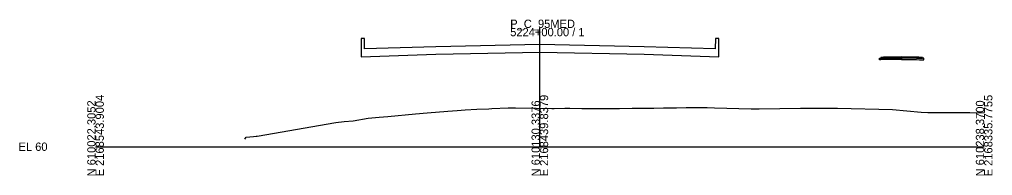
# Model space of a CAD drawing. Extents: x -26 to 303, y -10 to 10517.
# Drawn here: x -25.7 to 302.8, y 3990.3 to 4042.8 of the extents above; entities that cross this region are included whole.
import ezdxf

# ---------------------------------------------------------------- set-up
doc = ezdxf.new("R2010")
doc.units = 0
for name, color, linetype in [('RD_GPK_XS_Cell', 7, 'Continuous'), ('RD_PD_Final_TrvlWay', 7, 'Continuous'), ('RD_XS_Base', 7, 'Continuous'), ('RD_XS_ExGround', 7, 'Continuous'), ('RD_XS_Pave', 7, 'Continuous'), ('RD_XS_PaveOvlay_CP', 7, 'Continuous')]:
    doc.layers.add(name, color=color, linetype=linetype)

msp = doc.modelspace()

# ---------------------------------------------------------------- linework, layer by layer
at = {"layer": 'RD_GPK_XS_Cell'}
for p, q in [((150, 4000), (150, 4040)), ((0, 4000), (150, 4000)), ((150, 4000), (300, 4000))]:
    msp.add_line(p, q, dxfattribs=at)
at = {"layer": 'RD_PD_Final_TrvlWay'}
msp.add_lwpolyline([(114.83, 4031.13), (114.83, 4031.13), (150, 4031.83), (150, 4031.83), (150, 4031.83), (185.17, 4031.13), (185.17, 4031.13), (210.38, 4030.32), (210.38, 4036.41), (210.38, 4036.41), (209.25, 4036.41), (209.25, 4036.41), (209.25, 4036.41), (209.17, 4032.91), (185.17, 4033.69), (185.17, 4033.69), (150, 4034.39), (150, 4034.39), (150, 4034.39), (114.83, 4033.69), (114.83, 4033.69), (90.83, 4032.91), (90.75, 4036.41), (90.75, 4036.41), (90.75, 4036.41), (89.62, 4036.41), (89.62, 4036.41), (89.62, 4030.32), (114.83, 4031.13)], dxfattribs=at)
at = {"layer": 'RD_XS_Base'}
for points in [[(272.13, 4029.92), (272.13, 4029.42), (267.13, 4029.32), (265.13, 4029.28), (264.63, 4029.27), (264.63, 4029.77), (265.13, 4029.78), (267.13, 4029.82), (272.13, 4029.92)], [(274.95, 4029.86), (272.13, 4029.92), (272.13, 4030.01), (272.13, 4030.08), (272.13, 4029.79), (272.13, 4029.42), (274.95, 4029.36), (277.14, 4029.32), (278.21, 4029.3), (279.64, 4029.27), (279.64, 4029.48), (279.64, 4029.77), (279.35, 4029.77), (279.14, 4029.78), (278, 4029.8), (277.14, 4029.82), (274.95, 4029.86)]]:
    msp.add_lwpolyline(points, dxfattribs=at)
at = {"layer": 'RD_XS_ExGround'}
msp.add_lwpolyline([(50.39, 4002.51), (50.86, 4003.18), (53.28, 4003.45), (54.27, 4003.55), (54.29, 4003.56), (54.46, 4003.59), (54.49, 4003.6), (54.51, 4003.6), (54.54, 4003.6), (81.16, 4008.21), (83.92, 4008.47), (86.97, 4008.76), (92.04, 4009.64), (95.77, 4009.92), (98.69, 4010.16), (107.99, 4011.11), (111.94, 4011.45), (118.91, 4011.92), (122.06, 4012.16), (124.84, 4012.38), (128.72, 4012.59), (132.78, 4012.81), (133.81, 4012.85), (139.27, 4013.04), (141.81, 4013.12), (148.74, 4012.98), (154.04, 4012.84), (154.82, 4012.88), (158.42, 4012.98), (160.1, 4012.95), (164.17, 4012.89), (168.01, 4012.87), (173.69, 4012.89), (176.89, 4012.92), (181.14, 4012.96), (188.45, 4013.02), (191.75, 4013.1), (191.86, 4013.1), (194.48, 4013.12), (196.15, 4013.13), (199.44, 4013.18), (202.28, 4013.23), (204.55, 4013.23), (206.46, 4013.17), (208.98, 4013.09), (221.3, 4012.81), (222.95, 4012.81), (224.1, 4012.79), (237.97, 4012.95), (240.6, 4012.97), (247.42, 4012.99), (249.97, 4012.97), (250.5, 4012.98), (269.02, 4012.53), (278.7, 4011.59), (280.96, 4011.55), (287.15, 4011.52), (292.39, 4011.5), (292.44, 4011.5), (294.73, 4011.49), (295.14, 4011.48), (300, 4011.42)], dxfattribs=at)
at = {"layer": 'RD_XS_Pave'}
for points in [[(266.04, 4030.11), (265.13, 4030.1), (265.13, 4030.01), (265.13, 4029.94), (266.04, 4029.96), (267.13, 4029.98), (269.9, 4030.03), (272.13, 4030.08), (274.95, 4030.02), (277.14, 4029.98), (278, 4029.96), (279.14, 4029.94), (279.14, 4030.03), (279.14, 4030.1), (278, 4030.12), (277.14, 4030.14), (274.95, 4030.18), (272.13, 4030.24), (269.9, 4030.19), (267.13, 4030.14), (266.04, 4030.11)], [(265.13, 4029.94), (265.13, 4029.78), (267.13, 4029.82), (272.13, 4029.92), (272.13, 4030.08), (267.13, 4029.98), (265.13, 4029.94)], [(279.14, 4029.78), (279.14, 4029.94), (277.14, 4029.98), (272.13, 4030.08), (272.13, 4029.92), (277.14, 4029.82), (279.14, 4029.78)]]:
    msp.add_lwpolyline(points, dxfattribs=at)
at = {"layer": 'RD_XS_PaveOvlay_CP'}
msp.add_lwpolyline([(265.13, 4030.1), (267.13, 4030.14), (272.13, 4030.24), (277.14, 4030.14), (279.14, 4030.1)], dxfattribs=at)

# ---------------------------------------------------------------- texts
at = {"layer": 'RD_GPK_XS_Cell'}
for s, p in [('P_C_95MED', (140, 4040)), ('5224+00.00 / 1', (140, 4037.2)), ('EL 60', (-26, 3998.6))]:
    msp.add_text(s, height=2.8, dxfattribs=at).set_placement(p)
for s, p in [('N 610022.3052', (0, 3990)), ('E 2168543.9004', (2.8, 3990)), ('N 610130.3376', (150, 3990)), ('E 2168439.8379', (152.8, 3990)), ('N 610238.3700', (300, 3990)), ('E 2168335.7755', (302.8, 3990))]:
    msp.add_text(s, height=2.8, rotation=90, dxfattribs=at).set_placement(p)

doc.saveas('drawing.dxf')
